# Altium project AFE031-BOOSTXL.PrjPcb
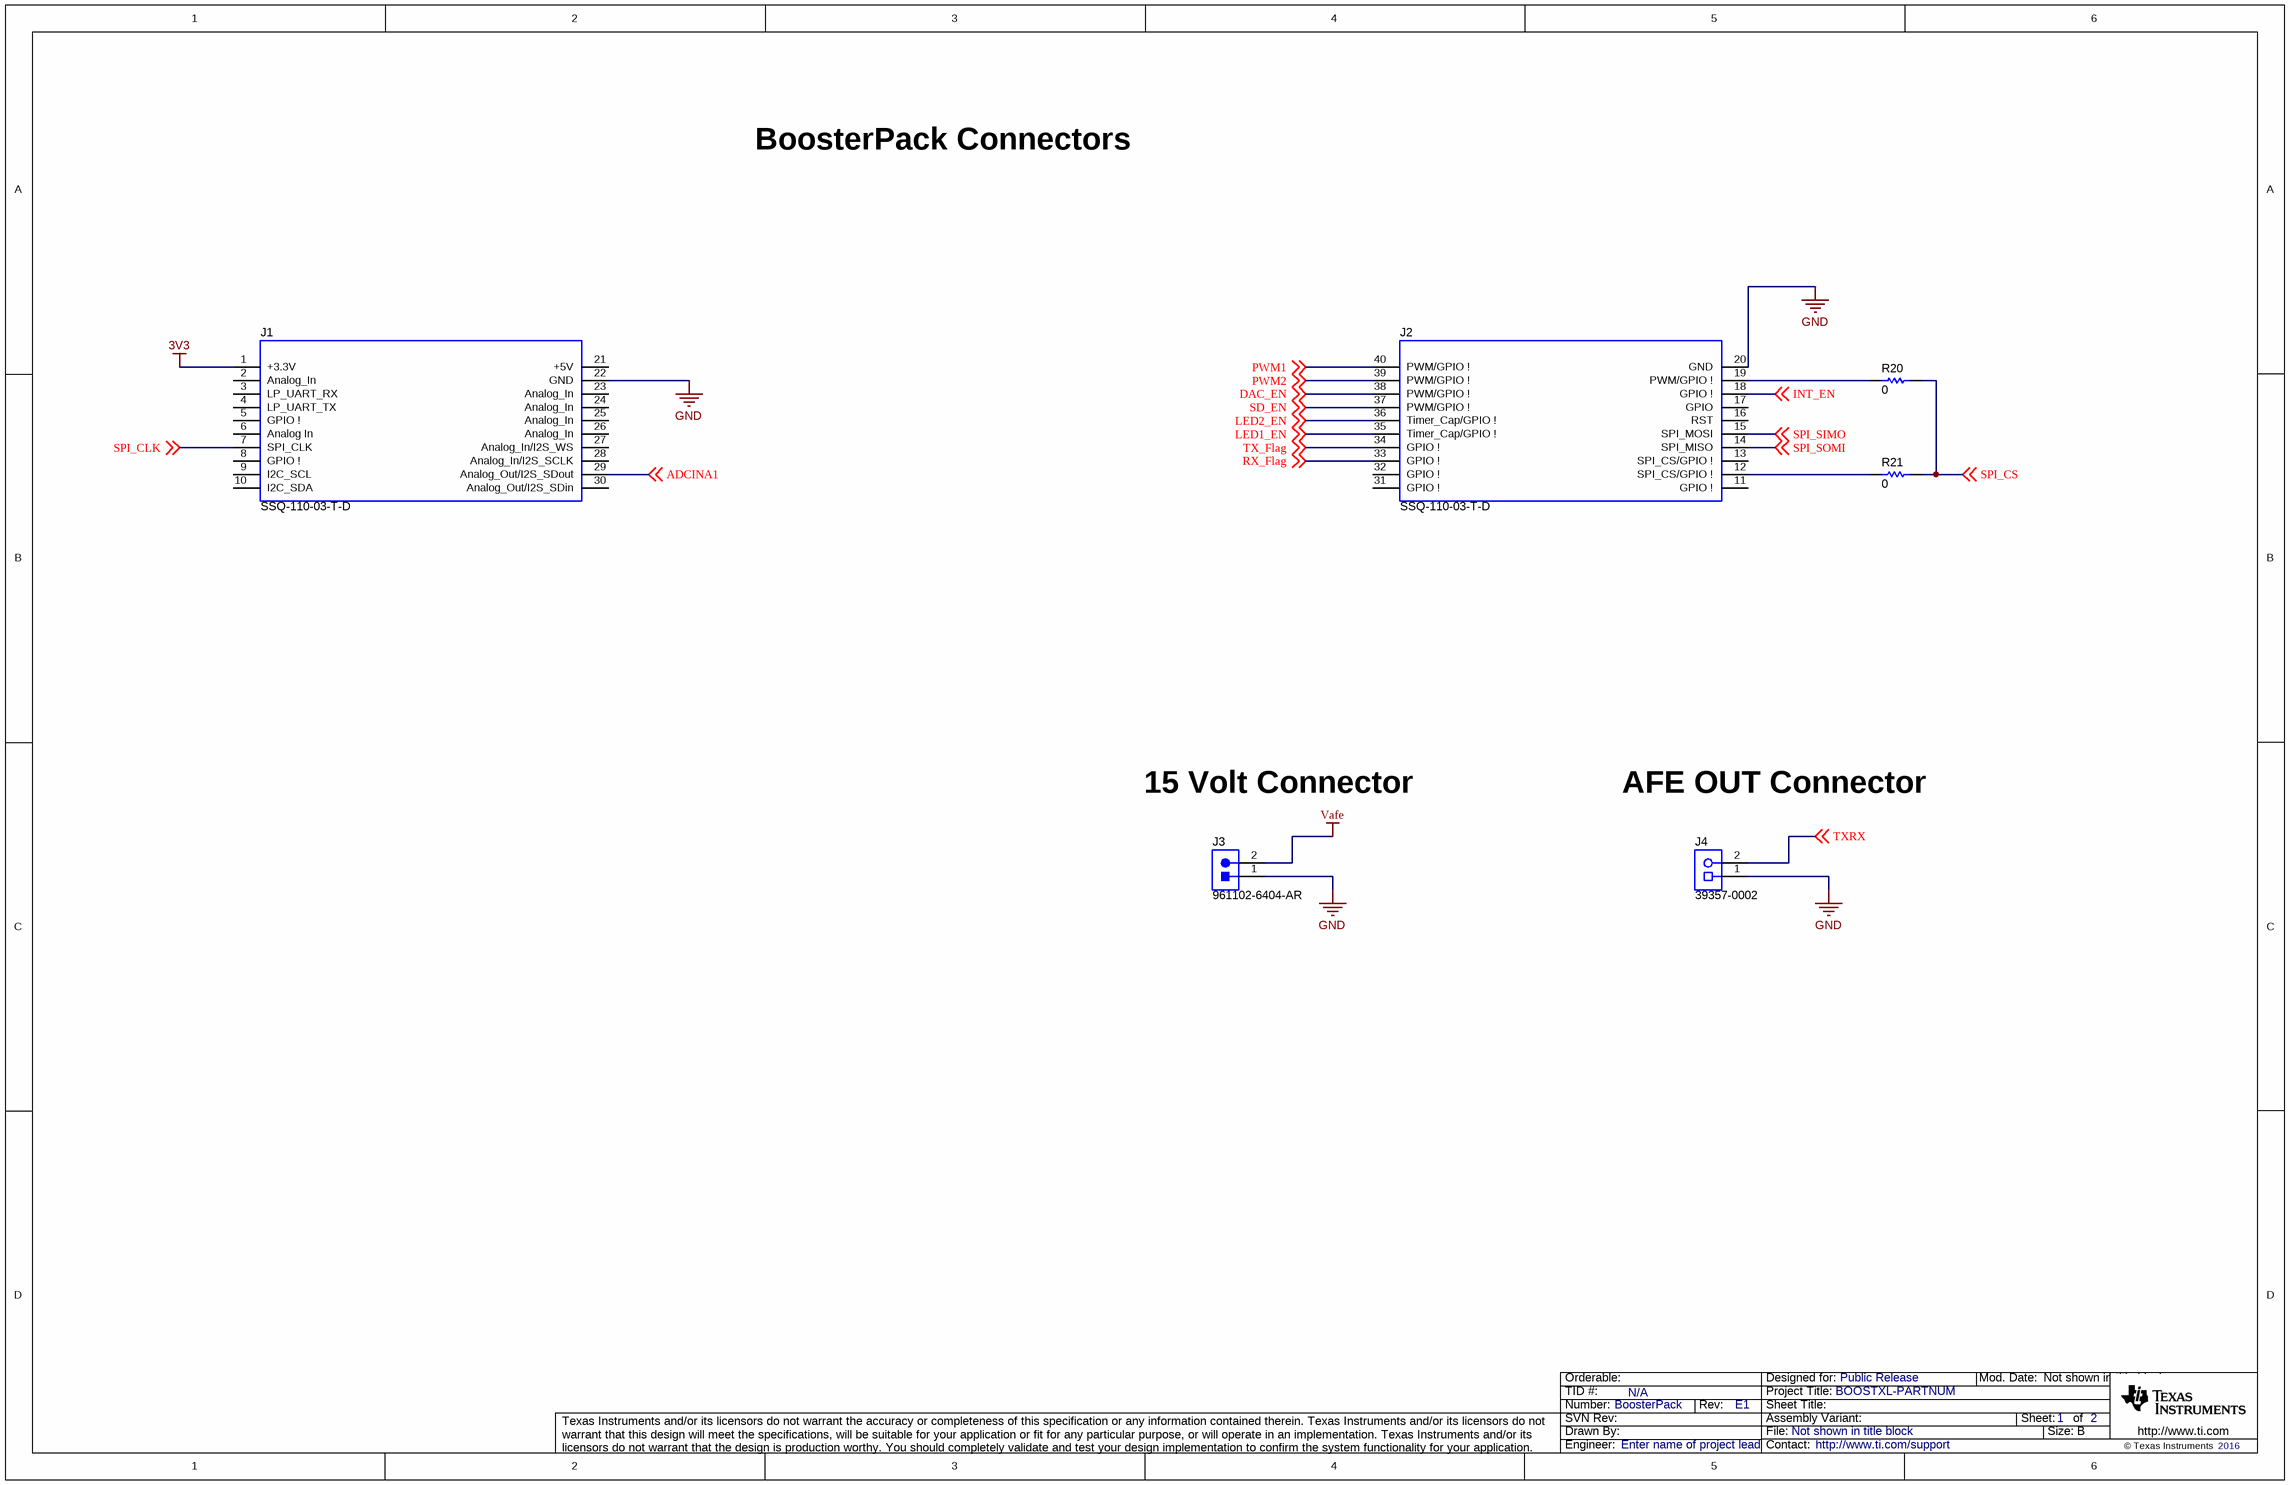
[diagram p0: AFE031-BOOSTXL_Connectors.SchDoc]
CopyrightYear: 2016; PCB_Layout: Who did the Layout?; PCB_Rev: E1; PRJ_Customer: Public Release; PRJ_Engineer: Enter name of project lead; PRJ_Number: BoosterPack; PRJ_Title: BOOSTXL-PARTNUM; SCH_Rev: E1; TechSupport: http://www.ti.com/support; TID: N/A
4 sheets, 93 parts. Net scope: global (net labels, ports and power ports of the same name join across sheets).
Board file: AFE031-BOOSTXL_PCB.PcbDoc
Sheets:
  AFE031-BOOSTXL_Connectors.SchDoc
  AFE031-BOOSTXL_EVM_Hardware.SchDoc
  AFE031-BOOSTXL_AFE.SchDoc
  AFE031-BOOSTXL_PassiveFilters.SchDoc

## Sheet AFE031-BOOSTXL_Connectors.SchDoc
size 431 x 279 mm; Date: Not shown in title block; ApprovedBy: Not shown in title block; CheckedBy: Not shown in title block; Author: Not shown in title block; CompanyName: Not shown in title block; Engineer: Not shown in title block; Organization: Not shown in title block; Address1: Not shown in title block; Address2: Not shown in title block; Address3: Not shown in title block; Address4: Not shown in title block; DocumentNumber: 1; Revision: Use project parameter SCH_Rev; SheetNumber: 1; SheetTotal: 2; PageSetup: Record=PageOptions¦CenterHorizontal=True¦CenterVertical=True¦PrintScale=1.00¦XCorrection=1.00¦YCorrection=1.00¦PrintKind=0¦BorderSize=5000000¦LeftOffset=0¦BottomOffset=0¦Orientation=2¦PaperLength=1000¦PaperWidth=1000¦Scale=100¦PaperSource=15¦PrintQuality=600¦MediaType=1¦DitherType=10¦PaperKind=Letter¦PrintScaleMode=1

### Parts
J1  SSQ-110-03-T-D  [BoosterPack_40pin_J1J3]
J2  SSQ-110-03-T-D  [BoosterPack_40pin_J2J4]
J3  961102-6404-AR  [3M_961102-6404-AR]
J4  39357-0002  [Molex_39357-0002]
R20  ValueDisplayed: 0  [0603]  (hidden comment: CRCW06030000Z0EA)
R21  ValueDisplayed: 0  [0603]  (hidden comment: CRCW06030000Z0EA)

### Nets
3V3: J1.1(+3.3V)
GND: J1.22(GND) J2.20(GND) J3.1 J4.1
Vafe: J3.2
ADCINA1: J1.29(Analog_Out/I2S_SDout) ; off-sheet ADCINA1
DAC_EN: J2.38(PWM/GPIO_!) ; off-sheet DAC_EN
INT_EN: J2.18(GPIO_!) ; off-sheet INT_EN
LED1_EN: J2.35(Timer_Cap/GPIO_!) ; off-sheet LED1_EN
LED2_EN: J2.36(Timer_Cap/GPIO_!) ; off-sheet LED2_EN
PWM1: J2.40(PWM/GPIO_!) ; off-sheet PWM1
PWM2: J2.39(PWM/GPIO_!) ; off-sheet PWM2
RX_Flag: J2.33(GPIO_!) ; off-sheet RX_Flag
SD_EN: J2.37(PWM/GPIO_!) ; off-sheet SD_EN
SPI_CLK: J1.7(SPI_CLK) ; off-sheet SPI_CLK
SPI_CS: R20.1 R21.1 ; off-sheet SPI_CS
SPI_SIMO: J2.15(SPI_MOSI) ; off-sheet SPI_SIMO
SPI_SOMI: J2.14(SPI_MISO) ; off-sheet SPI_SOMI
TX_Flag: J2.34(GPIO_!) ; off-sheet TX_Flag
TXRX: J4.2 ; off-sheet TXRX
NetJ2_12: J2.12(SPI_CS/GPIO_!) R21.2
NetJ2_19: J2.19(PWM/GPIO_!) R20.2

Not connected (* = marked no-connect by the designer): J1 2(Analog_In) 3(LP_UART_RX) 4(LP_UART_TX) 5(GPIO_!) 6(Analog_In) 8(GPIO_!) 9(I2C_SCL) 10(I2C_SDA) 21(+5V) 23(Analog_In) 24(Analog_In) 25(Analog_In) 26(Analog_In) 27(Analog_In/I2S_WS) 28(Analog_In/I2S_SCLK) 30(Analog_Out/I2S_SDin); J2 11(GPIO_!) 13(SPI_CS/GPIO_!) 16(RST) 17(GPIO) 31(GPIO_!) 32(GPIO_!)

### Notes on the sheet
- BoosterPack Connectors
- 15 Volt Connector
- AFE OUT Connector

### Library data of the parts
J1 = BoosterPack_40pin_J1J3: Receptacle, 2.54mm, 10x2, Tin, TH; Manufacturer: Samtec; Alternate Manufacturer: Major League Electronics; Alternate PartNumber: CRD-081413-A-G; SymbolCreator: a0412235; Note: Booster Pack 40 pin J1 and J3
J2 = BoosterPack_40pin_J2J4: Receptacle, 2.54mm, 10x2, Tin, TH; Manufacturer: Samtec; Alternate Manufacturer: Major League Electronics; Alternate PartNumber: CRD-081413-A-G; SymbolCreator: a0412235; Note: Booster Pack 40 pin J2 and J4
J3 = 961102-6404-AR: Header, 2.54mm, 2x1, TH; Manufacturer: 3M; SymbolCreator: a0412235; Pitch_mm: 2.54; Gender: Male; Shrouded: N; Row_Count: 1; ContactFinish: Gold; Current_A: 2; Voltage_V: 1000; Cert_UL: Y
J4 = 39357-0002: Terminal Block, 3.5 mm, 2x1, Tin, TH; Manufacturer: Molex; SymbolCreator: a0412235
R20 R21 = CRCW06030000Z0EA: RES, 0, 5%, 0.1 W, 0603; Manufacturer: Vishay-Dale; CompType: Resistor; Value: 0; Value_Code: 0000; Tolerance_%: 5; Power_W: 0.1; Value2: 0.1W; VDC_V: 75; TempCo: 200 ppm/C; SizeArea_mm2: 1.28; SizeX_mm: 1.6; SizeY_mm: 0.8; SizeZ_mm: 1; EIA_Code: E24; U/M: EA; AEC Category: Q200

## Sheet AFE031-BOOSTXL_EVM_Hardware.SchDoc
size 431 x 279 mm; Date: Not shown in title block; ApprovedBy: Not shown in title block; CheckedBy: Not shown in title block; Author: Not shown in title block; CompanyName: Not shown in title block; Engineer: Not shown in title block; Organization: Not shown in title block; Address1: Not shown in title block; Address2: Not shown in title block; Address3: Not shown in title block; Address4: Not shown in title block; DocumentNumber: 2; Revision: Use project parameter SCH_Rev; SheetNumber: 2; SheetTotal: 2; PageSetup: Record=PageOptions¦CenterHorizontal=True¦CenterVertical=True¦PrintScale=1.00¦XCorrection=1.00¦YCorrection=1.00¦PrintKind=0¦BorderSize=5000000¦LeftOffset=0¦BottomOffset=0¦Orientation=2¦PaperLength=1000¦PaperWidth=1000¦Scale=100¦PaperSource=15¦PrintQuality=600¦MediaType=1¦DitherType=10¦PaperKind=Letter¦PrintScaleMode=1
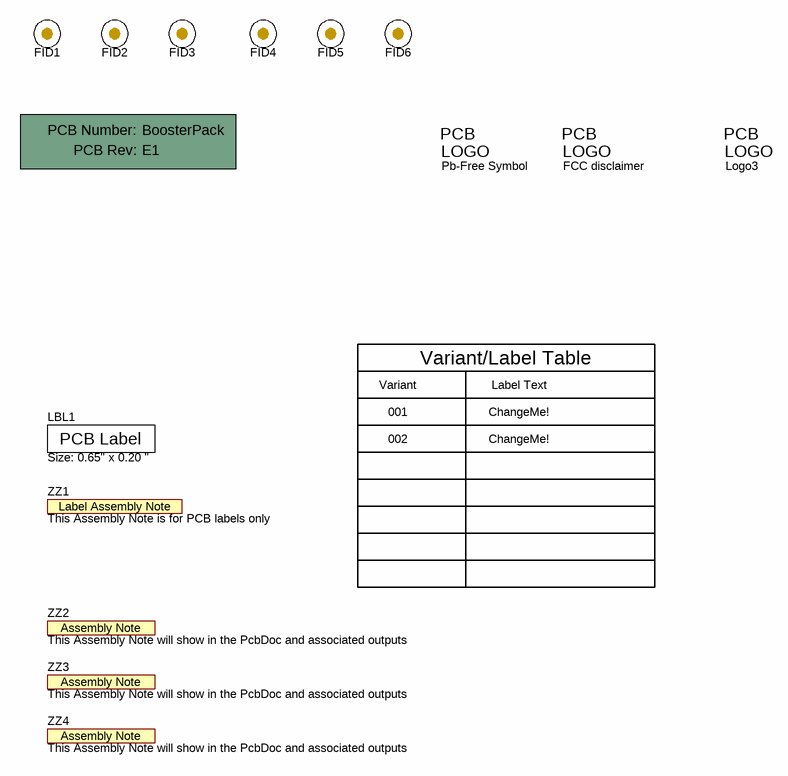
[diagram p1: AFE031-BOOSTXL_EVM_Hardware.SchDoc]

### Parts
!PCB1  Printed Circuit Board  (value not drawn)  (mechanical)
FID1  Fiducial  [Fiducial10-30]  (value not drawn)
FID2  Fiducial  [Fiducial10-30]  (value not drawn)
FID3  Fiducial  [Fiducial10-30]  (value not drawn)
FID4  Fiducial  [Fiducial10-30]  (value not drawn)
FID5  Fiducial  [Fiducial10-30]  (value not drawn)
FID6  Fiducial  [Fiducial10-30]  (value not drawn)
LBL1  Size: 0.65" x 0.20 "  [Label_650x200]
Logo1  Pb-Free Symbol  [Pb-Free_Overlay_Medium]  (no BOM)
Logo2  FCC disclaimer  [FCC_disclaimer]  (no BOM)
Logo3  Texas Instruments  [TI_Stacked_Overlay_Small]  (value not drawn)  (no BOM)
ZZ1  This Assembly Note is for PCB labels only  [AssemblyNoteLabel]  (no BOM)
ZZ2  This Assembly Note will show in the PcbDoc and associated outputs  [AssemblyNote]  (no BOM)
ZZ3  This Assembly Note will show in the PcbDoc and associated outputs  [AssemblyNote]  (no BOM)
ZZ4  This Assembly Note will show in the PcbDoc and associated outputs  [AssemblyNote]  (no BOM)

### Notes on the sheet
- Variant
- Variant/Label Table
- Label Text
- 001
- 002
- ChangeMe!

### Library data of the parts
!PCB1 = PCB: Manufacturer: Any; PartNumber: BoosterPack; SymbolCreator: a0412235
FID1-FID6 = Fiducial: Fiducial mark.  There is nothing to buy or mount.; SymbolCreator: codlsc
LBL1 = THT-14-423-10: Thermal Transfer Printable Labels, 0.650" W x 0.200" H - 10,000 per roll; Manufacturer: Brady; SymbolCreator: a0412235; CompType: Label
Logo1 = Pb-Free: SymbolCreator: a0412235
Logo2 = FCC_disclaimer: SymbolCreator: a0412235
Logo3 = TI_Logo: Texas Instrument Corporate Signature; SymbolCreator: a0412235
ZZ1 = AssemblyNoteLabel: SymbolCreator: a0412235
ZZ2-ZZ4 = AssemblyNote: SymbolCreator: codlsc

## Sheet AFE031-BOOSTXL_AFE.SchDoc
size 431 x 279 mm; Date: Not shown in title block; ApprovedBy: Not shown in title block; CheckedBy: Not shown in title block; Author: Not shown in title block; CompanyName: Not shown in title block; Engineer: Not shown in title block; Organization: Not shown in title block; Address1: Not shown in title block; Address2: Not shown in title block; Address3: Not shown in title block; Address4: Not shown in title block; DocumentNumber: 1; Revision: Use project parameter SCH_Rev; SheetNumber: 2; SheetTotal: 3; PageSetup: Record=PageOptions¦CenterHorizontal=True¦CenterVertical=True¦PrintScale=1.00¦XCorrection=1.00¦YCorrection=1.00¦PrintKind=0¦BorderSize=5000000¦LeftOffset=0¦BottomOffset=0¦Orientation=2¦PaperLength=1000¦PaperWidth=1000¦Scale=100¦PaperSource=15¦PrintQuality=600¦MediaType=1¦DitherType=10¦PaperKind=Letter¦PrintScaleMode=1
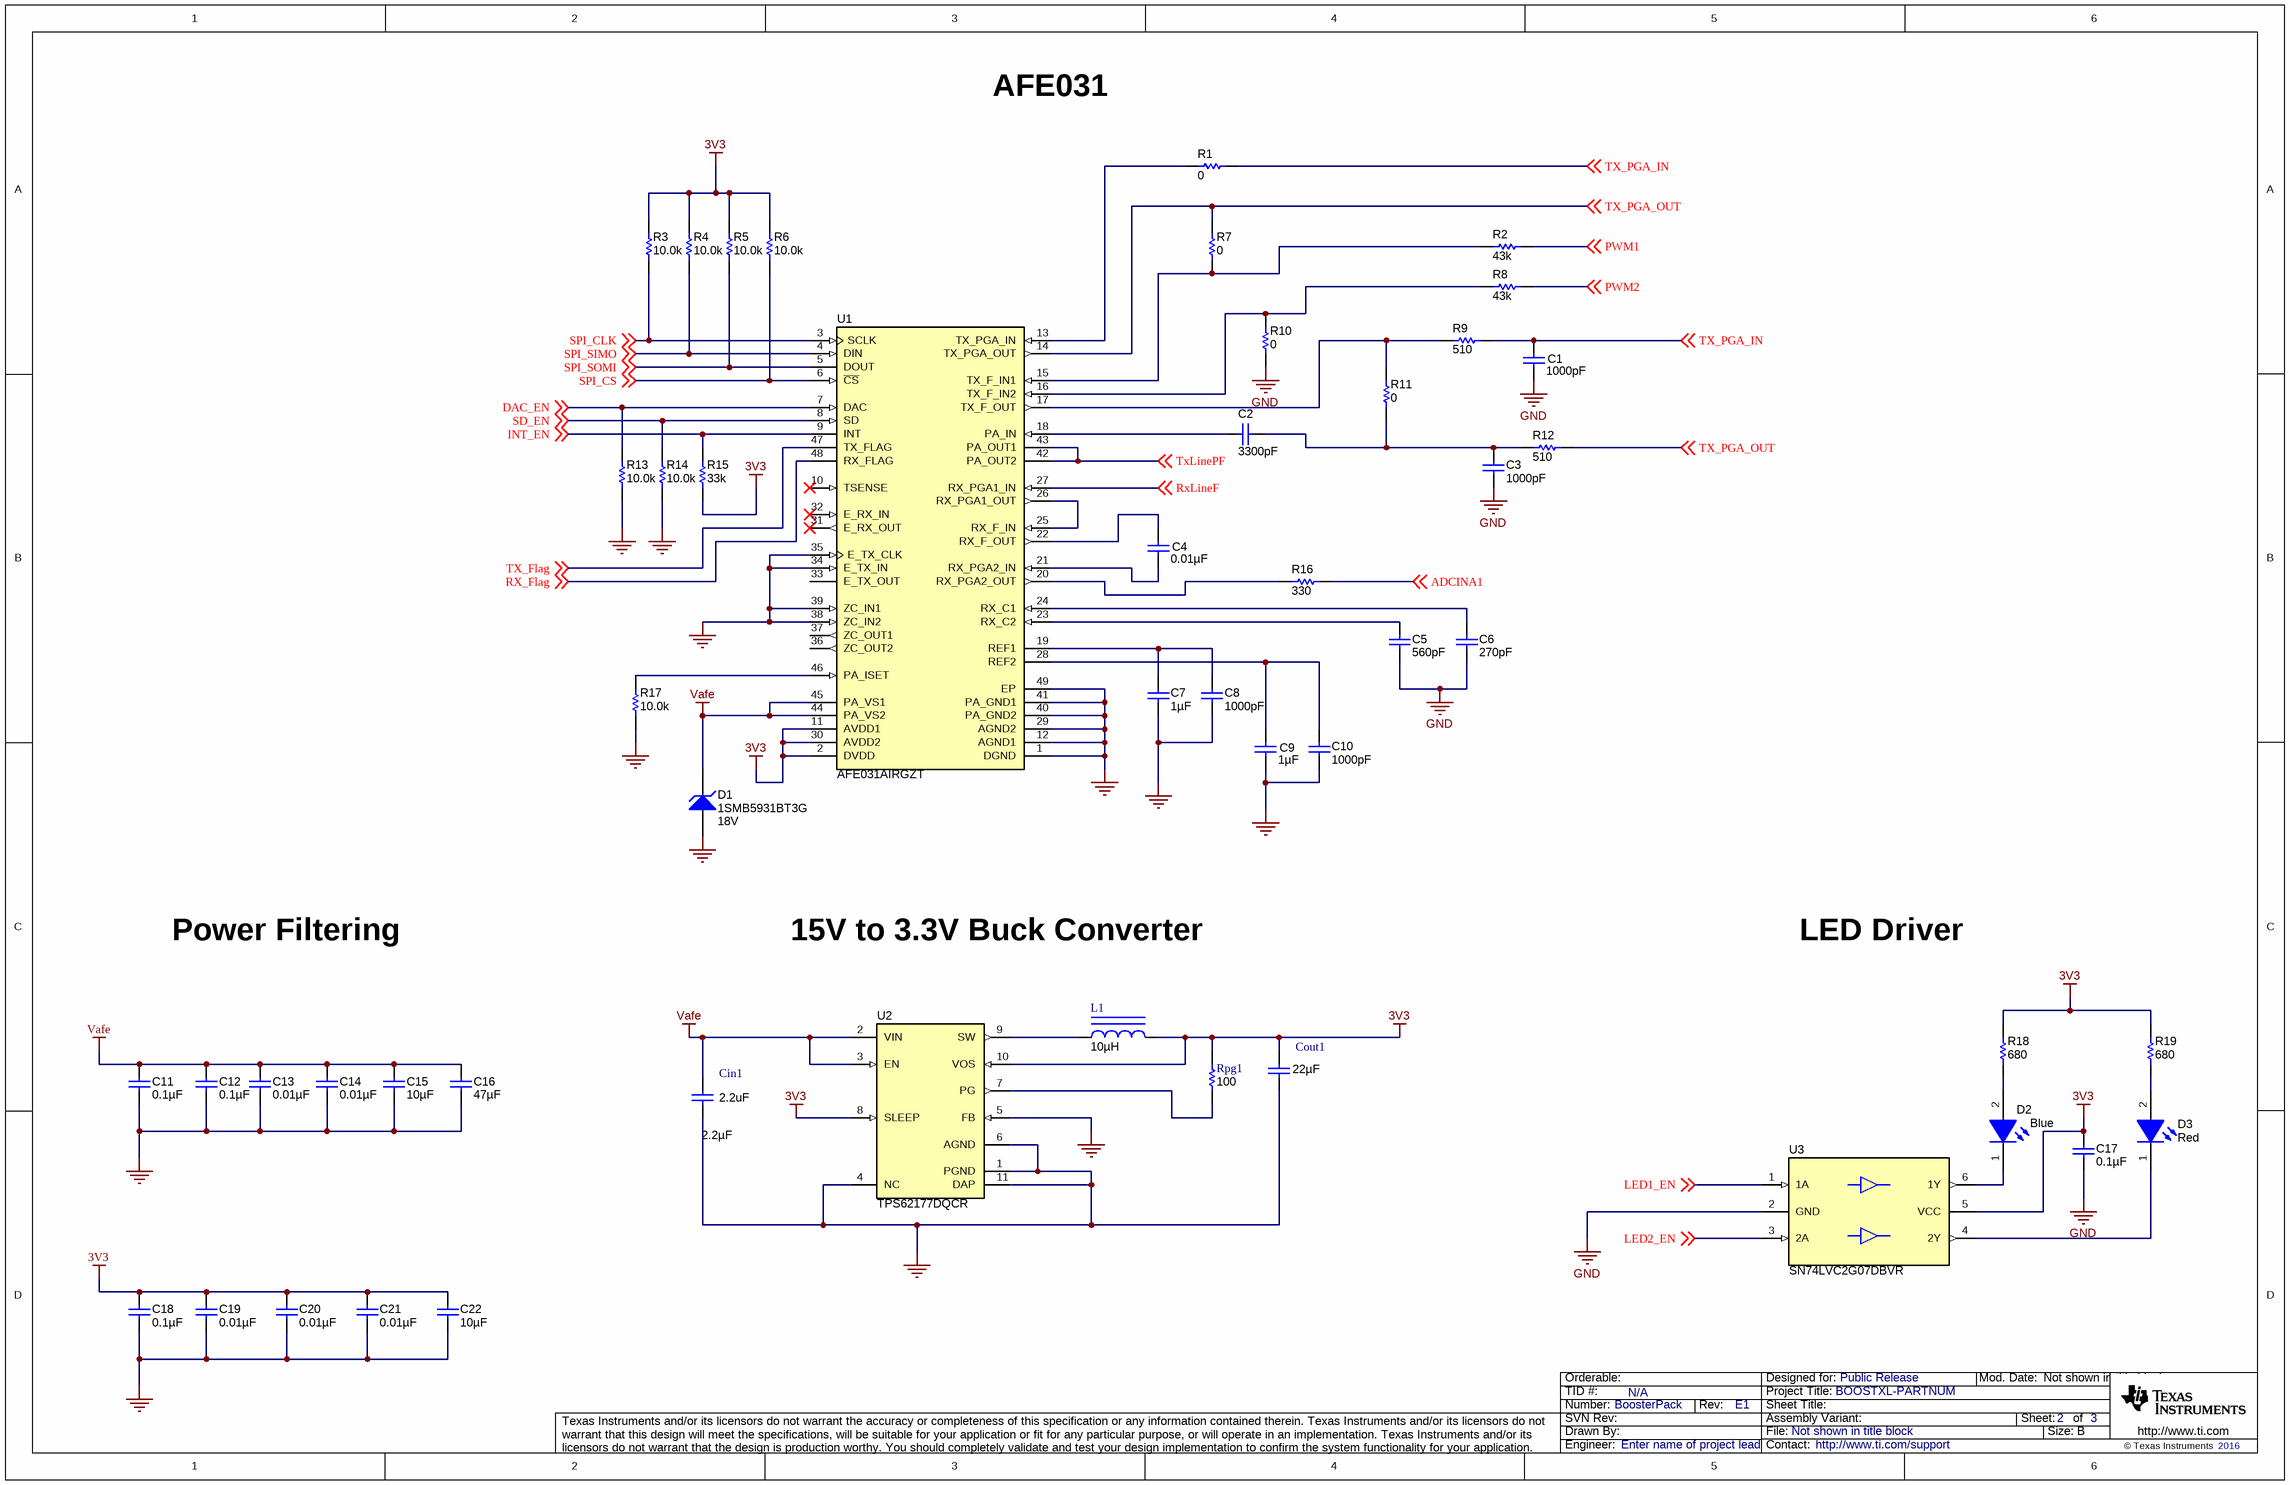
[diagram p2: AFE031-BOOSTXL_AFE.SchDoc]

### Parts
C1  ValueDisplayed: 1000pF  [1812]  (hidden comment: GR443QR73D102KW01L)
C2  ValueDisplayed: 3300pF  [0603]  (hidden comment: GRM1885C1H332JA01D)
C3  ValueDisplayed: 1000pF  [1812]  (hidden comment: GR443QR73D102KW01L)
C4  ValueDisplayed: 0.01µF  [0603]  (hidden comment: GRM188R71C103KA01D)
C5  ValueDisplayed: 560pF  [0603]  (hidden comment: GRM1885C1H561JA01D)
C6  ValueDisplayed: 270pF  [0603]  (hidden comment: 06035A271JAT2A)
C7  ValueDisplayed: 1µF  [0603]  (hidden comment: UMK107AB7105KA-T)
C8  ValueDisplayed: 1000pF  [0603]  (hidden comment: GRM188R71C102KA01D)
C9  ValueDisplayed: 1µF  [0603]  (hidden comment: UMK107AB7105KA-T)
C10  ValueDisplayed: 1000pF  [0603]  (hidden comment: GRM188R71C102KA01D)
C11  ValueDisplayed: 0.1µF  [0402_065]  (hidden comment: 160R07X104KV4T)
C12  ValueDisplayed: 0.1µF  [0402_065]  (hidden comment: 160R07X104KV4T)
C13  ValueDisplayed: 0.01µF  [0603]  (hidden comment: GRM188R71C103KA01D)
C14  ValueDisplayed: 0.01µF  [0603]  (hidden comment: GRM188R71C103KA01D)
C15  ValueDisplayed: 10µF  [0603]  (hidden comment: GRT188R61E106ME13D)
C16  ValueDisplayed: 47µF  [0805_HV]  (hidden comment: JMK212BJ476MG-T)
C17  ValueDisplayed: 0.1µF  [0603]  (hidden comment: 0603YC104JAT2A)
C18  ValueDisplayed: 0.1µF  [0402_065]  (hidden comment: 160R07X104KV4T)
C19  ValueDisplayed: 0.01µF  [0603]  (hidden comment: GRM188R71C103KA01D)
C20  ValueDisplayed: 0.01µF  [0603]  (hidden comment: GRM188R71C103KA01D)
C21  ValueDisplayed: 0.01µF  [0603]  (hidden comment: GRM188R71C103KA01D)
C22  ValueDisplayed: 10µF  [0603]  (hidden comment: GRT188R61E106ME13D)
Cin1  value 2.2uF  ValueDisplayed: 2.2µF  [1206]  (hidden comment: GRM31MR71E225KA93L)
Cout1  ValueDisplayed: 22µF  [0805_HV]  (hidden comment: GRM21BR60J226ME39L)
D1  1SMB5931BT3G  value 18V  [SMB]
D2  value Blue  [WL-SMCW_Blue]  (hidden comment: 150060BS75000)
D3  value Red  [WL-SMCW_RED]  (hidden comment: 150060RS75000)
L1  ValueDisplayed: 10µH  [LPS4018]  (hidden comment: LPS4018-103MRB)
R1  ValueDisplayed: 0  [0603]  (hidden comment: CRCW06030000Z0EA)
R2  ValueDisplayed: 43k  [0603]  (hidden comment: CRCW060343K0JNEA)
R3  ValueDisplayed: 10.0k  [0402]  (hidden comment: CRCW040210K0FKED)
R4  ValueDisplayed: 10.0k  [0402]  (hidden comment: CRCW040210K0FKED)
R5  ValueDisplayed: 10.0k  [0402]  (hidden comment: CRCW040210K0FKED)
R6  ValueDisplayed: 10.0k  [0402]  (hidden comment: CRCW040210K0FKED)
R7  ValueDisplayed: 0  [0603]  (hidden comment: CRCW06030000Z0EA)
R8  ValueDisplayed: 43k  [0603]  (hidden comment: CRCW060343K0JNEA)
R9  ValueDisplayed: 510  [0603]  (hidden comment: RC0603JR-07510RL)
R10  ValueDisplayed: 0  [0603]  (hidden comment: CRCW06030000Z0EA)
R11  ValueDisplayed: 0  [0603]  (hidden comment: CRCW06030000Z0EA)
R12  ValueDisplayed: 510  [0603]  (hidden comment: RC0603JR-07510RL)
R13  ValueDisplayed: 10.0k  [0402]  (hidden comment: CRCW040210K0FKED)
R14  ValueDisplayed: 10.0k  [0402]  (hidden comment: CRCW040210K0FKED)
R15  ValueDisplayed: 33k  [0402]  (hidden comment: CRCW040233K0JNED)
R16  ValueDisplayed: 330  [0402]  (hidden comment: CRCW0402330RJNED)
R17  ValueDisplayed: 10.0k  [0402]  (hidden comment: CRCW040210K0FKED)
R18  ValueDisplayed: 680  [0603]  (hidden comment: CRCW0603680RJNEA)
R19  ValueDisplayed: 680  [0603]  (hidden comment: CRCW0603680RJNEA)
Rpg1  ValueDisplayed: 100  [0402]  (hidden comment: ERJ-2RKF1000X)
U1  AFE031AIRGZT  [RGZ0048B - Thicker Vias]
U2  TPS62177DQCR  [DQC0010A-Edited]
U3  SN74LVC2G07DBVR  [DBV0006A_N]

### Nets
3V3: C17.1 C18.1 C19.1 C20.1 C21.1 C22.2 Cout1.1 L1.2 R3.2 R4.2 R5.2 R6.2 R15.1 R18.2 R19.2 Rpg1.1 U1.2(DVDD) U1.11(AVDD1) U1.30(AVDD2) U2.8(SLEEP) U2.10(VOS) U3.5(VCC)
GND: C1.2 C3.2 C5.2 C6.2 C7.2 C8.2 C9.2 C10.2 C11.2 C12.2 C13.2 C14.2 C15.1 C16.2 C17.2 C18.2 C19.2 C20.2 C21.2 C22.1 Cin1.2 Cout1.2 D1.2(A) R10.1 R13.1 R14.1 R17.1 U1.1(DGND) U1.12(AGND1) U1.29(AGND2) U1.34(E_TX_IN) U1.35(E_TX_CLK) U1.38(ZC_IN2) U1.39(ZC_IN1) U1.40(PA_GND2) U1.41(PA_GND1) U1.49(EP) U2.1(PGND) U2.4(NC) U2.5(FB) U2.6(AGND) U2.11(DAP) U3.2(GND)
Vafe: C11.1 C12.1 C13.1 C14.1 C15.2 C16.1 Cin1.1 D1.1(K) U1.44(PA_VS2) U1.45(PA_VS1) U2.2(VIN) U2.3(EN)
ADCINA1: R16.2 ; off-sheet ADCINA1
DAC_EN: R13.2 U1.7(DAC) ; off-sheet DAC_EN
INT_EN: R15.2 U1.9(INT) ; off-sheet INT_EN
LED1_EN: U3.1(1A) ; off-sheet LED1_EN
LED2_EN: U3.3(2A) ; off-sheet LED2_EN
PWM1: R2.2 ; off-sheet PWM1
PWM2: R8.2 ; off-sheet PWM2
RX_Flag: U1.48(RX_FLAG) ; off-sheet RX_Flag
RxLineF: U1.27(RX_PGA1_IN) ; off-sheet RxLineF
SD_EN: R14.2 U1.8(SD) ; off-sheet SD_EN
SPI_CLK: R3.1 U1.3(SCLK) ; off-sheet SPI_CLK
SPI_CS: R6.1 U1.6(~{CS}) ; off-sheet SPI_CS
SPI_SIMO: R4.1 U1.4(DIN) ; off-sheet SPI_SIMO
SPI_SOMI: R5.1 U1.5(DOUT) ; off-sheet SPI_SOMI
TX_Flag: U1.47(TX_FLAG) ; off-sheet TX_Flag
TX_PGA_IN: C1.1 R1.2 R9.2 ; off-sheet TX_PGA_IN
TX_PGA_OUT: R7.2 R12.2 U1.14(TX_PGA_OUT) ; off-sheet TX_PGA_OUT
TxLinePF: U1.42(PA_OUT2) U1.43(PA_OUT1) ; off-sheet TxLinePF
NetC2_1: C2.1 C3.1 R11.1 R12.1
NetC2_2: C2.2 U1.18(PA_IN)
NetC4_1: C4.1 U1.22(RX_F_OUT)
NetC4_2: C4.2 U1.21(RX_PGA2_IN)
NetC5_1: C5.1 U1.23(RX_C2)
NetC6_1: C6.1 U1.24(RX_C1)
NetC7_1: C7.1 C8.1 U1.19(REF1)
NetC9_1: C9.1 C10.1 U1.28(REF2)
NetD2_1: D2.1(K) U3.6(1Y)
NetD2_2: D2.2(A) R18.1
NetD3_1: D3.1(K) U3.4(2Y)
NetD3_2: D3.2(A) R19.1
NetL1_1: L1.1 U2.9(SW)
NetR1_1: R1.1 U1.13(TX_PGA_IN)
NetR2_1: R2.1 R7.1 U1.15(TX_F_IN1)
NetR8_1: R8.1 R10.2 U1.16(TX_F_IN2)
NetR9_1: R9.1 R11.2 U1.17(TX_F_OUT)
NetR16_1: R16.1 U1.20(RX_PGA2_OUT)
NetR17_2: R17.2 U1.46(PA_ISET)
NetRpg1_2: Rpg1.2 U2.7(PG)
NetU1_25: U1.25(RX_F_IN) U1.26(RX_PGA1_OUT)

Not connected (* = marked no-connect by the designer): U1 10(TSENSE)* 31(E_RX_OUT)* 32(E_RX_IN)* 33(E_TX_OUT) 36(ZC_OUT2) 37(ZC_OUT1)

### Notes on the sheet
- AFE031
- Power Filtering
- 15V to 3.3V Buck Converter
- LED Driver

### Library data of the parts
C1 C3 = GR443QR73D102KW01L: CAP, CERM, 1000 pF, 2000 V, +/- 10%, X7R, 1812; Manufacturer: MuRata; Polarized: N; CompType: Capacitor; Value: 1000pF; U/M: EA; Cap_F: 0.000000001; Tolerance_%: 10; Value1: Unknown; VDC_V: 2000; Value2: 2000V; TaMin_C: -55; TaMax_C: 125; SizeArea_mm2: 14.4; SizeAreaWB_mm2: 23.1; SizeX_mm: 4.5; SizeY_mm: 3.2; SizeZ_mm: 1.35; AEC Category: Q200
C2 = GRM1885C1H332JA01D: CAP, CERM, 3300 pF, 50 V, +/- 5%, C0G/NP0, 0603; Manufacturer: MuRata; Polarized: N; CompType: Capacitor; Value: 3300pF; U/M: EA; Cap_F: 0.0000000033; Tolerance_%: 5; Value1: Unknown; VDC_V: 50; Value2: 50V; TaMin_C: -55; TaMax_C: 125; SizeArea_mm2: 1.28; SizeAreaWB_mm2: 4.68; SizeX_mm: 1.6; SizeY_mm: 0.8; SizeZ_mm: 1; AEC Category: Q200
C4 C13 C14 C19-C21 = GRM188R71C103KA01D: CAP, CERM, 0.01 µF, 16 V, +/- 10%, X7R, 0603; Manufacturer: MuRata; Polarized: N; CompType: Capacitor; Value: 0.01uF; U/M: EA; Cap_F: 0.00000001; Tolerance_%: 10; Value1: Unknown; VDC_V: 16; Value2: 16V; TaMin_C: -55; TaMax_C: 125; SizeArea_mm2: 1.28; SizeAreaWB_mm2: 4.68; SizeX_mm: 1.6; SizeY_mm: 0.8; SizeZ_mm: 1; AEC Category: Q200
C5 = GRM1885C1H561JA01D: CAP, CERM, 560 pF, 50 V, +/- 5%, C0G/NP0, 0603; Manufacturer: MuRata; Polarized: N; CompType: Capacitor; Value: 560pF; U/M: EA; Cap_F: 0.00000000056; Tolerance_%: 5; Value1: Unknown; VDC_V: 50; Value2: 50V; TaMin_C: -55; TaMax_C: 125; SizeArea_mm2: 1.28; SizeAreaWB_mm2: 4.68; SizeX_mm: 1.6; SizeY_mm: 0.8; SizeZ_mm: 1; AEC Category: Q200
C6 = 06035A271JAT2A: CAP, CERM, 270 pF, 50 V, +/- 5%, C0G/NP0, 0603; Manufacturer: AVX; Polarized: N; CompType: Capacitor; Value: 270pF; U/M: EA; Cap_F: 0.00000000027; Tolerance_%: 5; ESR_ohm: 0.077; Value1: 0.077 ohm; VDC_V: 50; Value2: 50V; TaMin_C: -55; TaMax_C: 125; SizeArea_mm2: 1.28; SizeAreaWB_mm2: 4.68; SizeX_mm: 1.6; SizeY_mm: 0.8; SizeZ_mm: 1; AEC Category: Q200
C7 C9 = UMK107AB7105KA-T: CAP, CERM, 1 µF, 50 V, +/- 10%, X7R, 0603; Manufacturer: Taiyo Yuden; Polarized: N; CompType: Capacitor; Value: 1uF; U/M: EA; Cap_F: 0.000001; Tolerance_%: 10; Value1: Unknown; VDC_V: 50; Value2: 50V; TaMin_C: -55; TaMax_C: 125; SizeArea_mm2: 1.28; SizeAreaWB_mm2: 4.68; SizeX_mm: 1.6; SizeY_mm: 0.8; SizeZ_mm: 1; AEC Category: Q200
C8 C10 = GRM188R71C102KA01D: CAP, CERM, 1000 pF, 16 V, +/- 10%, X7R, 0603; Manufacturer: MuRata; Polarized: N; CompType: Capacitor; Value: 1000pF; U/M: EA; Cap_F: 0.000000001; Tolerance_%: 10; Value1: Unknown; VDC_V: 16; Value2: 16V; TaMin_C: -55; TaMax_C: 125; SizeArea_mm2: 1.28; SizeAreaWB_mm2: 4.68; SizeX_mm: 1.6; SizeY_mm: 0.8; SizeZ_mm: 1; AEC Category: Q200
C11 C12 C18 = 160R07X104KV4T: CAP, CERM, 0.1 µF, 16 V, +/- 10%, X5R, 0402; Manufacturer: Johanson Technology; Polarized: N; CompType: Capacitor; Value: 0.1uF; U/M: EA; Cap_F: 0.0000001; Tolerance_%: 10; Value1: Unknown; VDC_V: 16; Value2: 16V; TaMin_C: -55; TaMax_C: 85; Cap_Case: 0402; SizeArea_mm2: 0.5; SizeAreaWB_mm2: 3; SizeX_mm: 1; SizeZ_mm: 0.65; AEC Category: Q200
C15 C22 = GRT188R61E106ME13D: CAP, CERM, 10 µF, 25 V, +/- 20%, X5R, 0603; Manufacturer: MuRata; Polarized: N; CompType: Capacitor; Value: 10uF; U/M: EA; Cap_F: 0.00001; Tolerance_%: 20; Value1: Unknown; VDC_V: 25; Value2: 25V; TaMin_C: -55; TaMax_C: 85; SizeArea_mm2: 1.28; SizeAreaWB_mm2: 4.68; SizeX_mm: 1.6; SizeY_mm: 0.8; SizeZ_mm: 1; AEC Category: Q200
C16 = JMK212BJ476MG-T: CAP, CERM, 47 µF, 6.3 V, +/- 20%, X5R, 0805; Manufacturer: Taiyo Yuden; Polarized: N; CompType: Capacitor; Value: 47uF; U/M: EA; Cap_F: 0.000047; Tolerance_%: 20; Value1: Unknown; VDC_V: 6.3; Value2: 6.3V; TaMin_C: -55; TaMax_C: 85; Cap_Case: 0805; SizeArea_mm2: 2.5; SizeAreaWB_mm2: 6.75; SizeX_mm: 2; SizeY_mm: 1.25; SizeZ_mm: 1.45; AEC Category: Q200
C17 = 0603YC104JAT2A: CAP, CERM, 0.1 µF, 16 V, +/- 5%, X7R, 0603; Manufacturer: AVX; Polarized: N; CompType: Capacitor; Value: 0.1uF; U/M: EA; Cap_F: 0.0000001; Tolerance_%: 5; ESR_ohm: 0.039; Value1: 0.039 ohm; VDC_V: 16; Value2: 16V; TaMin_C: -55; TaMax_C: 125; SizeArea_mm2: 1.28; SizeAreaWB_mm2: 4.68; SizeX_mm: 1.6; SizeY_mm: 0.8; SizeZ_mm: 1; AEC Category: Q200
Cin1 = GRM31MR71E225KA93L: CAP, CERM, 2.2 µF, 25 V, +/- 10%, X7R, 1206; Manufacturer: MuRata; Polarized: N; CompType: Capacitor; U/M: EA; Cap_F: 0.0000022; Tolerance_%: 10; Value1: Unknown; VDC_V: 25; Value2: 25V; TaMin_C: -55; TaMax_C: 125; Cap_Case: 1210; SizeArea_mm2: 5.12; SizeAreaWB_mm2: 10.92; SizeX_mm: 3.2; SizeY_mm: 1.6; SizeZ_mm: 1.35; AEC Category: Q200
Cout1 = GRM21BR60J226ME39L: CAP, CERM, 22 µF, 6.3 V, +/- 20%, X5R, 0805; Manufacturer: MuRata; Polarized: N; CompType: Capacitor; U/M: EA; Cap_F: 0.000022; Tolerance_%: 20; ESR_ohm: 0.009; Value1: 0.009 ohm; VDC_V: 6.3; Value2: 6.3V; IRMS_A: 3.5; TaMin_C: -55; TaMax_C: 85; Cap_Case: 0805; SizeArea_mm2: 2.5; SizeAreaWB_mm2: 6.75; SizeX_mm: 2; SizeY_mm: 1.25; SizeZ_mm: 1.45; AEC Category: Q200; Value: 22uF
D1 = 1SMB5931BT3G: Diode, Zener, 18 V, 550 mW, SMB; Manufacturer: ON Semiconductor; SymbolCreator: a0412235; U/M: EA; Power_W: 0.55; Vz_V: 18; Value1: 0.55W; RJA_CperW: 226; SizeAreaWB_mm2: 44.156; SizeArea_mm2: 21.336; SizeX_mm: 5.6; SizeY_mm: 3.81; SizeZ_mm: 2.6; AEC Category: Q101
D2 = 150060BS75000: LED, Blue, SMD; Manufacturer: Wurth Elektronik; Type: InGaN; Vf_V: 3.2; Value2: 3.2V; Io_A: 0.03; Vr_V: 5; Tjmax_C: 85; Power_TotalModule: 0.105; Value1: 0.105W; Angle: 140; U/M: EA
D3 = 150060RS75000: LED, Red, SMD; Manufacturer: Wurth Elektronik; Type: AlInGaP; Vf_V: 2; Value2: 2V; Io_A: 0.03; Vr_V: 5; Tjmax_C: 85; Power_TotalModule: 0.072; Value1: 0.072W; Angle: 140; U/M: EA
L1 = LPS4018-103MRB: Inductor, Shielded Drum Core, Ferrite, 10 µH, 1.25 A, 0.18 ohm, SMD; Manufacturer: Coilcraft; Value: 10uH; Ind_H: 10.0E-6; Imax_A: 1.25; Irms: 1.25A @ 40C rise; Isat: 1.3A @ 30% inductance drop; DCR_ohm: 0.18; Value2: 1.25A; SizeAreaWB_mm2: 24.01; SizeArea_mm2: 15.21; SizeX_mm: 3.9; SizeZ_mm: 1.7; AEC Category: Q200; AEC Qualified: N
R1 R7 R10 R11 = CRCW06030000Z0EA: as R20 on sheet AFE031-BOOSTXL_Connectors
R2 R8 = CRCW060343K0JNEA: RES, 43 k, 5%, 0.1 W, 0603; Manufacturer: Vishay-Dale; CompType: Resistor; Value: 43k; Res_ohm: 43000; Value_Code: 43k0; Tolerance_%: 5; Power_W: 0.1; Value2: 0.1W; VDC_V: 75; TempCo: 200 ppm/C; SizeArea_mm2: 1.28; SizeX_mm: 1.6; SizeY_mm: 0.8; SizeZ_mm: 1; EIA_Code: E24; U/M: EA; AEC Category: Q200
R3-R6 R13 R14 R17 = CRCW040210K0FKED: RES, 10.0 k, 1%, 0.063 W, 0402; Manufacturer: Vishay-Dale; CompType: Resistor; Value: 10.0k; Res_ohm: 10000; Value_Code: 10k0; Tolerance_%: 1; Power_W: 0.063; Value2: 0.063W; VDC_V: 50; TempCo: 100 ppm/C; SizeArea_mm2: 0.5; SizeZ_mm: 0.6; EIA_Code: E96; U/M: EA; AEC Category: Q200
R9 R12 = RC0603JR-07510RL: RES, 510, 5%, 0.1 W, 0603; Manufacturer: Yageo America; CompType: Resistor; Value: 510; Value_Code: 510R; Tolerance_%: 5; Power_W: 0.1; Value2: 0.1W; VDC_V: 50; TempCo: 100 ppm/C; SizeArea_mm2: 1.28; SizeX_mm: 1.6; SizeY_mm: 0.8; SizeZ_mm: 1; EIA_Code: E24; U/M: EA; AEC Category: Q200
R15 = CRCW040233K0JNED: RES, 33 k, 5%, 0.063 W, 0402; Manufacturer: Vishay-Dale; CompType: Resistor; Value: 33k; Res_ohm: 33000; Value_Code: 33k0; Tolerance_%: 5; Power_W: 0.063; Value2: 0.063W; VDC_V: 50; TempCo: 200 ppm/C; SizeArea_mm2: 0.5; SizeX_mm: 1; SizeZ_mm: 0.6; EIA_Code: E24; U/M: EA; AEC Category: Q200
R16 = CRCW0402330RJNED: RES, 330, 5%, 0.063 W, 0402; Manufacturer: Vishay-Dale; CompType: Resistor; Value: 330; Value_Code: 330R; Tolerance_%: 5; Power_W: 0.063; Value2: 0.063W; VDC_V: 50; TempCo: 200 ppm/C; SizeArea_mm2: 0.5; SizeX_mm: 1; SizeZ_mm: 0.6; EIA_Code: E24; U/M: EA; AEC Category: Q200
R18 R19 = CRCW0603680RJNEA: RES, 680, 5%, 0.1 W, 0603; Manufacturer: Vishay-Dale; CompType: Resistor; Value: 680; Value_Code: 680R; Tolerance_%: 5; Power_W: 0.1; Value2: 0.1W; VDC_V: 75; TempCo: 200 ppm/C; SizeArea_mm2: 1.28; SizeX_mm: 1.6; SizeY_mm: 0.8; SizeZ_mm: 1; EIA_Code: E24; U/M: EA; AEC Category: Q200
Rpg1 = ERJ-2RKF1000X: RES, 100, 1%, 0.1 W, 0402; Manufacturer: Panasonic; CompType: Resistor; Value_Code: 100R; Tolerance_%: 1; Power_W: 0.1; Value2: 0.1W; VDC_V: 50; TempCo: 100 ppm/C; SizeArea_mm2: 0.5; SizeZ_mm: 0.6; EIA_Code: E96; U/M: EA; AEC Category: Q200; Value: 100
U1 = AFE031AIRGZT: Powerline Communications Analog Front End, 7 to 26 V, -40 to 125 degC, 48-pin QFN (RGZ0048B), Green (RoHS & no Sb/Br); Manufacturer: Texas Instruments; Alternate PartNumber: Equivalent; GBW(Typ)(MHz): 4.4; Iq per channel(Max)(mA): 60.3; Packing: SMALL T&R; Rating: Catalog; Slew Rate(Typ)(V/us): 19; Sub Family: Precision Amplifier; Total Supply Voltage(Max)(+5V is 5, +/-5V is 10): 26; Total Supply Voltage(Min)(+5V is 5, +/-5V is 10): 7
U2 = TPS62177DQCR: 28V, 0.5A Step-Down Converter with SNOOZE Mode, DQC0010A (WSON-10); Alternate PartNumber: TPS62177DQCT; Manufacturer: Texas Instruments; SymbolCreator: a0799628; SizeArea_mm2: 6; SizeAreaWB_mm2: 12; SizeX_mm: 2; SizeY_mm: 3; SizeZ_mm: 0.8; CompType: IC; U/M: EA
U3 = SN74LVC2G07DBVR: Dual Buffer/Driver with Open-Drain Output, DBV0006A (SOT-6); Manufacturer: Texas Instruments; SymbolCreator: x0208326; SizeArea_mm2: 8.12; SizeAreaWB_mm2: 14.82; SizeX_mm: 2.8; SizeY_mm: 2.9; SizeZ_mm: 1.45; CompType: IC; U/M: EA

## Sheet AFE031-BOOSTXL_PassiveFilters.SchDoc
size 431 x 279 mm; Date: Not shown in title block; ApprovedBy: Not shown in title block; CheckedBy: Not shown in title block; Author: Not shown in title block; CompanyName: Not shown in title block; Engineer: Not shown in title block; Organization: Not shown in title block; Address1: Not shown in title block; Address2: Not shown in title block; Address3: Not shown in title block; Address4: Not shown in title block; DocumentNumber: 1; Revision: Use project parameter SCH_Rev; SheetNumber: 2; SheetTotal: 3; PageSetup: Record=PageOptions¦CenterHorizontal=True¦CenterVertical=True¦PrintScale=1.00¦XCorrection=1.00¦YCorrection=1.00¦PrintKind=0¦BorderSize=5000000¦LeftOffset=0¦BottomOffset=0¦Orientation=2¦PaperLength=1000¦PaperWidth=1000¦Scale=100¦PaperSource=15¦PrintQuality=600¦MediaType=1¦DitherType=10¦PaperKind=Letter¦PrintScaleMode=1
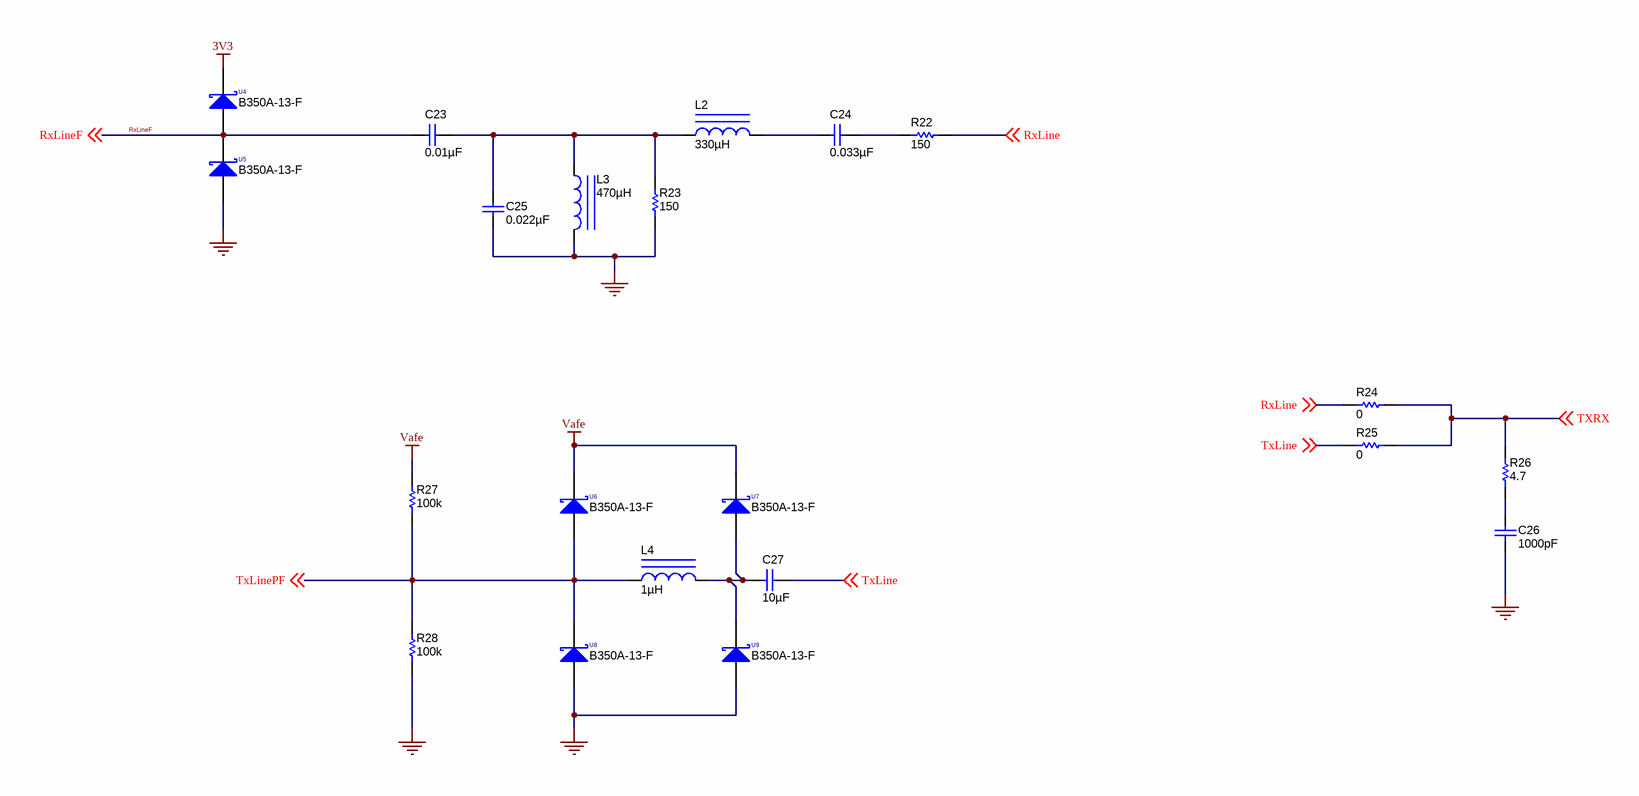
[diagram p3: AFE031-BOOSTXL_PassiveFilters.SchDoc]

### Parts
C23  ValueDisplayed: 0.01µF  [0603]  (hidden comment: GCM188R71H103KA37D)
C24  ValueDisplayed: 0.033µF  [0603]  (hidden comment: 06035C333JAT2A)
C25  ValueDisplayed: 0.022µF  [0603]  (hidden comment: GRM188R71H223KA01D)
C26  ValueDisplayed: 1000pF  [0603]  (hidden comment: 06035A102KAT2A)
C27  ValueDisplayed: 10µF  [1206_180]  (hidden comment: GRT31CR61H106KE01L)
L2  ValueDisplayed: 330µH  [DO1608C]  (hidden comment: DO1608C-334MLB)
L3  ValueDisplayed: 470µH  [DO1608C]  (hidden comment: DO1608C-474MLB)
L4  ValueDisplayed: 1µH  [LQH2MC_52]  (hidden comment: LQH2MCN1R0M52)
R22  ValueDisplayed: 150  [0603]  (hidden comment: CRCW0603150RFKEA)
R23  ValueDisplayed: 150  [0603]  (hidden comment: CRCW0603150RFKEA)
R24  ValueDisplayed: 0  [0603]  (hidden comment: CRCW06030000Z0EA)
R25  ValueDisplayed: 0  [0603]  (hidden comment: CRCW06030000Z0EA)
R26  ValueDisplayed: 4.7  [0805_HV]  (hidden comment: ERJ-6GEYJ4R7V)
R27  ValueDisplayed: 100k  [0603]  (hidden comment: RC0603FR-07100KL)
R28  ValueDisplayed: 100k  [0603]  (hidden comment: RC0603FR-07100KL)
U4  B350A-13-F  [SMA]
U5  B350A-13-F  [SMA]
U6  B350A-13-F  [SMA]
U7  B350A-13-F  [SMA]
U8  B350A-13-F  [SMA]
U9  B350A-13-F  [SMA]

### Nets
3V3: U4.1(K)
GND: C25.2 C26.2 L3.2 R23.1 R28.1 U5.2(A) U8.2(A) U9.2(A)
Vafe: R27.2 U6.1(K) U7.1(K)
RxLine: R22.1 R24.2 ; off-sheet RxLine
RxLineF: C23.2 U4.2(A) U5.1(K) ; off-sheet RxLineF
TxLine: C27.1 R25.2 ; off-sheet TxLine
TxLinePF: L4.1 R27.1 R28.2 U6.2(A) U8.1(K) ; off-sheet TxLinePF
TXRX: R24.1 R25.1 R26.2 ; off-sheet TXRX
NetC23_1: C23.1 C25.1 L2.1 L3.1 R23.2
NetC24_1: C24.1 R22.2
NetC24_2: C24.2 L2.2
NetC26_1: C26.1 R26.1
NetC27_2: C27.2 L4.2 U7.2(A) U9.1(K)

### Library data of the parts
C23 = GCM188R71H103KA37D: CAP, CERM, 0.01 µF, 50 V, +/- 10%, X7R, AEC-Q200 Grade 1, 0603; Manufacturer: MuRata; Polarized: N; CompType: Capacitor; Value: 0.01uF; U/M: EA; Cap_F: 0.00000001; Tolerance_%: 10; Value1: Unknown; VDC_V: 50; Value2: 50V; TaMin_C: -55; TaMax_C: 125; SizeArea_mm2: 1.28; SizeAreaWB_mm2: 4.68; SizeX_mm: 1.6; SizeY_mm: 0.8; SizeZ_mm: 1; AEC Category: Q200; AEC Qualified: Y
C24 = 06035C333JAT2A: CAP, CERM, 0.033 µF, 50 V, +/- 5%, X7R, 0603; Manufacturer: AVX; Polarized: N; CompType: Capacitor; Value: 0.033uF; U/M: EA; Cap_F: 0.000000033; Tolerance_%: 5; Value1: Unknown; VDC_V: 50; Value2: 50V; TaMin_C: -55; TaMax_C: 125; SizeArea_mm2: 1.28; SizeAreaWB_mm2: 4.68; SizeX_mm: 1.6; SizeY_mm: 0.8; SizeZ_mm: 1; AEC Category: Q200
C25 = GRM188R71H223KA01D: CAP, CERM, 0.022 µF, 50 V, +/- 10%, X7R, 0603; Manufacturer: MuRata; Polarized: N; CompType: Capacitor; Value: 0.022uF; U/M: EA; Cap_F: 0.000000022; Tolerance_%: 10; Value1: Unknown; VDC_V: 50; Value2: 50V; TaMin_C: -55; TaMax_C: 125; SizeArea_mm2: 1.28; SizeAreaWB_mm2: 4.68; SizeX_mm: 1.6; SizeY_mm: 0.8; SizeZ_mm: 1; AEC Category: Q200
C26 = 06035A102KAT2A: CAP, CERM, 1000 pF, 50 V, +/- 10%, C0G/NP0, 0603; Manufacturer: AVX; Polarized: N; CompType: Capacitor; Value: 1000pF; U/M: EA; Cap_F: 0.000000001; Tolerance_%: 10; ESR_ohm: 0.048; Value1: 0.048 ohm; VDC_V: 50; Value2: 50V; TaMin_C: -55; TaMax_C: 125; SizeArea_mm2: 1.28; SizeAreaWB_mm2: 4.68; SizeX_mm: 1.6; SizeY_mm: 0.8; SizeZ_mm: 1; AEC Category: Q200
C27 = GRT31CR61H106KE01L: CAP, CERM, 10 µF, 50 V, +/- 10%, X5R, AEC-Q200 Grade 1, 1206; Manufacturer: MuRata; Polarized: N; CompType: Capacitor; Value: 10uF; U/M: EA; Cap_F: 0.00001; Tolerance_%: 10; Value1: Unknown; VDC_V: 50; Value2: 50V; TaMin_C: -55; TaMax_C: 85; Cap_Case: 1206; SizeArea_mm2: 5.12; SizeAreaWB_mm2: 10.92; SizeX_mm: 3.2; SizeY_mm: 1.6; SizeZ_mm: 1.8; AEC Category: Q200; AEC Qualified: Y; AEC Grade: 1
L2 = DO1608C-334MLB: Inductor, Drum Core, Ferrite, 330 µH, 0.18 A, 3.8 ohm, SMD; Manufacturer: Coilcraft; Value: 330uH; Ind_H: 330.0E-6; Imax_A: 0.18; Irms: 0.3A @ 15C rise; Isat: 0.18A @ 10% inductance drop; DCR_ohm: 3.8; Value1: 3.8 ohm; Value2: 0.18A; SizeAreaWB_mm2: 55.47; SizeArea_mm2: 29.37; SizeX_mm: 6.6; SizeY_mm: 4.45; SizeZ_mm: 2.92; AEC Category: Q200
L3 = DO1608C-474MLB: Inductor, Drum Core, Ferrite, 470 µH, 0.16 A, 5.06 ohm, SMD; Manufacturer: Coilcraft; Value: 470uH; Ind_H: 470.0E-6; Imax_A: 0.16; Irms: 0.26A @ 15C rise; Isat: 0.16A @ 10% inductance drop; DCR_ohm: 5.06; Value2: 0.16A; SizeAreaWB_mm2: 55.47; SizeArea_mm2: 29.37; SizeX_mm: 6.6; SizeY_mm: 4.45; SizeZ_mm: 2.92; AEC Category: Q200
L4 = LQH2MCN1R0M52: Inductor, Wirewound, Ferrite, 1 µH, 0.595 A, 0.25 ohm, SMD; Manufacturer: MuRata; Value: 1uH; Ind_H: 1.0E-6; Imax_A: 0.595; Irms: 0.595A @ 40C rise; DCR_ohm: 0.25; Value2: 0.595A; SizeAreaWB_mm2: 7.8; SizeArea_mm2: 3.2; SizeX_mm: 2; SizeY_mm: 1.6; SizeZ_mm: 0.7; AEC Category: Q200
R22 R23 = CRCW0603150RFKEA: RES, 150, 1%, 0.1 W, 0603; Manufacturer: Vishay-Dale; CompType: Resistor; Value: 150; Value_Code: 150R; Tolerance_%: 1; Power_W: 0.1; Value2: 0.1W; VDC_V: 75; TempCo: 100 ppm/C; SizeArea_mm2: 1.28; SizeX_mm: 1.6; SizeY_mm: 0.8; EIA_Code: E96; U/M: EA; AEC Category: Q200
R24 R25 = CRCW06030000Z0EA: as R20 on sheet AFE031-BOOSTXL_Connectors
R26 = ERJ-6GEYJ4R7V: RES, 4.7, 5%, 0.125 W, 0805; Manufacturer: Panasonic; CompType: Resistor; Value: 4.7; Value_Code: 4R70; Tolerance_%: 5; Power_W: 0.125; Value2: 0.125W; VDC_V: 150; TempCo: 600 ppm/C; SizeArea_mm2: 2.5; SizeX_mm: 2; SizeY_mm: 1.25; SizeZ_mm: 1.45; EIA_Code: E24; U/M: EA; AEC Category: Q200
R27 R28 = RC0603FR-07100KL: RES, 100 k, 1%, 0.1 W, 0603; Manufacturer: Yageo America; CompType: Resistor; Value: 100k; Res_ohm: 100000; Tolerance_%: 1; Power_W: 0.1; Value2: 0.1W; VDC_V: 150; TempCo: 200 ppm/C; SizeArea_mm2: 1.28; SizeX_mm: 1.6; SizeY_mm: 0.8; EIA_Code: E96; U/M: EA; AEC Category: Q200
U4-U9 = B350A-13-F: Diode, Schottky, 50 V, 3 A, SMA; Manufacturer: Diodes Inc.; U/M: EA; Vf_V: 0.7; Value: 50V; Value1: 3A; Value2: 0.7V; Io_A: 3; Vr_V: 50; TJmax_C: 125; RJC_CperW: 25; SizeAreaWB_mm2: 37.3428; SizeArea_mm2: 16.3228; SizeX_mm: 5.59; SizeY_mm: 2.92; SizeZ_mm: 2.87; AEC Category: Q101

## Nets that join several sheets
3V3: AFE031-BOOSTXL_Connectors (J1.1), AFE031-BOOSTXL_AFE (22 pins), AFE031-BOOSTXL_PassiveFilters (U4.1)
GND: AFE031-BOOSTXL_Connectors (J1.22 J2.20 J3.1 J4.1), AFE031-BOOSTXL_AFE (43 pins), AFE031-BOOSTXL_PassiveFilters (8 pins)
Vafe: AFE031-BOOSTXL_Connectors (J3.2), AFE031-BOOSTXL_AFE (12 pins), AFE031-BOOSTXL_PassiveFilters (R27.2 U6.1 U7.1)
ADCINA1: AFE031-BOOSTXL_Connectors (J1.29), AFE031-BOOSTXL_AFE (R16.2)
DAC_EN: AFE031-BOOSTXL_Connectors (J2.38), AFE031-BOOSTXL_AFE (R13.2 U1.7)
INT_EN: AFE031-BOOSTXL_Connectors (J2.18), AFE031-BOOSTXL_AFE (R15.2 U1.9)
LED1_EN: AFE031-BOOSTXL_Connectors (J2.35), AFE031-BOOSTXL_AFE (U3.1)
LED2_EN: AFE031-BOOSTXL_Connectors (J2.36), AFE031-BOOSTXL_AFE (U3.3)
PWM1: AFE031-BOOSTXL_Connectors (J2.40), AFE031-BOOSTXL_AFE (R2.2)
PWM2: AFE031-BOOSTXL_Connectors (J2.39), AFE031-BOOSTXL_AFE (R8.2)
RX_Flag: AFE031-BOOSTXL_Connectors (J2.33), AFE031-BOOSTXL_AFE (U1.48)
RxLineF: AFE031-BOOSTXL_AFE (U1.27), AFE031-BOOSTXL_PassiveFilters (C23.2 U4.2 U5.1)
SD_EN: AFE031-BOOSTXL_Connectors (J2.37), AFE031-BOOSTXL_AFE (R14.2 U1.8)
SPI_CLK: AFE031-BOOSTXL_Connectors (J1.7), AFE031-BOOSTXL_AFE (R3.1 U1.3)
SPI_CS: AFE031-BOOSTXL_Connectors (R20.1 R21.1), AFE031-BOOSTXL_AFE (R6.1 U1.6)
SPI_SIMO: AFE031-BOOSTXL_Connectors (J2.15), AFE031-BOOSTXL_AFE (R4.1 U1.4)
SPI_SOMI: AFE031-BOOSTXL_Connectors (J2.14), AFE031-BOOSTXL_AFE (R5.1 U1.5)
TX_Flag: AFE031-BOOSTXL_Connectors (J2.34), AFE031-BOOSTXL_AFE (U1.47)
TxLinePF: AFE031-BOOSTXL_AFE (U1.42 U1.43), AFE031-BOOSTXL_PassiveFilters (5 pins)
TXRX: AFE031-BOOSTXL_Connectors (J4.2), AFE031-BOOSTXL_PassiveFilters (R24.1 R25.1 R26.2)

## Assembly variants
PWM_Mode: not fitted FID1 FID2 FID3 R21 R? R? R? R? U6 U7
DAC_Mode: not fitted C1 C3 FID1 FID2 FID3 R1 R2 R8 R9 R12 R20 R? U7 U9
